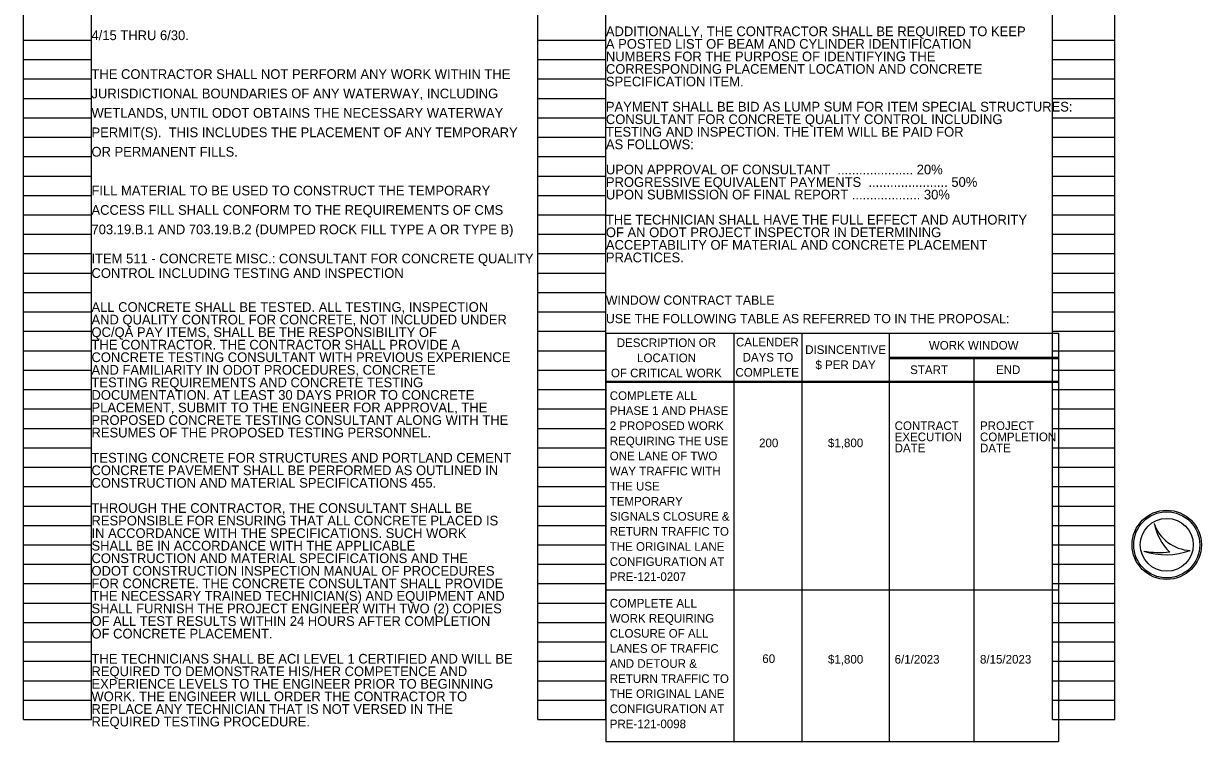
# Model space of a CAD drawing. Extents: x 0 to 78.9, y -24.2 to 22.
# Drawn here: x 61.9 to 78.89, y -23.54 to -13.19 of the extents above; entities that cross this region are included whole.
import ezdxf

# ---------------------------------------------------------------- set-up
doc = ezdxf.new("R2010")
doc.units = 0
doc.layers.add('SH_Data', color=7, linetype='Continuous')
doc.layers.add('SH_Text', color=7, linetype='Continuous')

msp = doc.modelspace()

# ---------------------------------------------------------------- linework, layer by layer
at = {"layer": 'SH_Data'}
for p, q in [((61.904, -23.228), (61.904, -3.068)), ((62.884, -23.228), (62.884, -3.068)), ((69.324, -23.228), (69.324, -3.068)), ((70.304, -23.228), (70.304, -3.068)), ((76.744, -23.228), (76.744, -3.068)), ((77.644, -23.228), (77.644, -3.068)), ((61.904, -13.428), (62.884, -13.428)), ((69.324, -13.428), (70.304, -13.428)), ((76.744, -13.428), (77.644, -13.428)), ((61.904, -13.708), (62.884, -13.708)), ((69.324, -13.708), (70.304, -13.708)), ((76.744, -13.708), (77.644, -13.708)), ((61.904, -13.988), (62.884, -13.988)), ((69.324, -13.988), (70.304, -13.988)), ((76.744, -13.988), (77.644, -13.988)), ((61.904, -14.268), (62.884, -14.268)), ((69.324, -14.268), (70.304, -14.268)), ((76.744, -14.268), (77.644, -14.268)), ((61.904, -14.548), (62.884, -14.548)), ((69.324, -14.548), (70.304, -14.548)), ((76.744, -14.548), (77.644, -14.548)), ((61.904, -14.828), (62.884, -14.828)), ((69.324, -14.828), (70.304, -14.828)), ((76.744, -14.828), (77.644, -14.828)), ((61.904, -15.108), (62.884, -15.108)), ((69.324, -15.108), (70.304, -15.108)), ((76.744, -15.108), (77.644, -15.108)), ((61.904, -15.388), (62.884, -15.388)), ((69.324, -15.388), (70.304, -15.388)), ((76.744, -15.388), (77.644, -15.388)), ((61.904, -15.668), (62.884, -15.668)), ((69.324, -15.668), (70.304, -15.668)), ((76.744, -15.668), (77.644, -15.668)), ((61.904, -15.948), (62.884, -15.948)), ((69.324, -15.948), (70.304, -15.948)), ((76.744, -15.948), (77.644, -15.948)), ((61.904, -16.228), (62.884, -16.228)), ((69.324, -16.228), (70.304, -16.228)), ((76.744, -16.228), (77.644, -16.228)), ((61.904, -16.508), (62.884, -16.508)), ((69.324, -16.508), (70.304, -16.508)), ((76.744, -16.508), (77.644, -16.508)), ((61.904, -16.788), (62.884, -16.788)), ((69.324, -16.788), (70.304, -16.788)), ((76.744, -16.788), (77.644, -16.788)), ((61.904, -17.068), (62.884, -17.068)), ((69.324, -17.068), (70.304, -17.068)), ((76.744, -17.068), (77.644, -17.068)), ((61.904, -17.348), (62.884, -17.348)), ((69.324, -17.348), (70.304, -17.348)), ((76.744, -17.348), (77.644, -17.348)), ((61.904, -17.628), (62.884, -17.628)), ((69.324, -17.628), (70.304, -17.628)), ((70.304, -17.657), (76.833, -17.657)), ((70.304, -17.657), (70.304, -23.544)), ((72.149, -17.657), (72.149, -18.46)), ((73.13, -17.657), (73.13, -18.46)), ((74.392, -17.657), (74.392, -18.46)), ((76.744, -17.628), (77.644, -17.628)), ((76.833, -17.657), (76.833, -18.477)), ((61.904, -17.908), (62.884, -17.908)), ((69.324, -17.908), (70.304, -17.908)), ((74.392, -18.002), (76.833, -18.002)), ((76.744, -17.908), (77.644, -17.908)), ((74.392, -18.02), (76.833, -18.02)), ((75.613, -18.02), (75.613, -23.544)), ((61.904, -18.188), (62.884, -18.188)), ((69.324, -18.188), (70.304, -18.188)), ((70.304, -18.347), (76.833, -18.347)), ((76.744, -18.188), (77.644, -18.188)), ((76.833, -18.347), (76.833, -23.544)), ((61.904, -18.468), (62.884, -18.468)), ((69.324, -18.468), (70.304, -18.468)), ((70.304, -18.364), (76.833, -18.364)), ((72.149, -18.364), (72.149, -23.544)), ((73.13, -18.364), (73.13, -23.544)), ((74.392, -18.364), (74.392, -23.544)), ((76.744, -18.468), (77.644, -18.468)), ((61.904, -18.748), (62.884, -18.748)), ((69.324, -18.748), (70.304, -18.748)), ((76.744, -18.748), (77.644, -18.748)), ((61.904, -19.028), (62.884, -19.028)), ((69.324, -19.028), (70.304, -19.028)), ((76.744, -19.028), (77.644, -19.028)), ((61.904, -19.308), (62.884, -19.308)), ((69.324, -19.308), (70.304, -19.308)), ((76.744, -19.308), (77.644, -19.308)), ((61.904, -19.588), (62.884, -19.588)), ((69.324, -19.588), (70.304, -19.588)), ((76.744, -19.588), (77.644, -19.588)), ((61.904, -19.868), (62.884, -19.868)), ((69.324, -19.868), (70.304, -19.868)), ((76.744, -19.868), (77.644, -19.868)), ((61.904, -20.148), (62.884, -20.148)), ((69.324, -20.148), (70.304, -20.148)), ((76.744, -20.148), (77.644, -20.148)), ((61.904, -20.428), (62.884, -20.428)), ((69.324, -20.428), (70.304, -20.428)), ((76.744, -20.428), (77.644, -20.428)), ((78.212, -20.398), (78.212, -20.398)), ((61.904, -20.708), (62.884, -20.708)), ((69.324, -20.708), (70.304, -20.708)), ((76.744, -20.708), (77.644, -20.708)), ((78.062, -20.798), (78.062, -20.798)), ((78.732, -20.789), (78.732, -20.789)), ((61.904, -20.988), (62.884, -20.988)), ((69.324, -20.988), (70.304, -20.988)), ((76.744, -20.988), (77.644, -20.988)), ((61.904, -21.268), (62.884, -21.268)), ((69.324, -21.268), (70.304, -21.268)), ((70.304, -21.358), (76.833, -21.358)), ((76.744, -21.268), (77.644, -21.268)), ((61.904, -21.548), (62.884, -21.548)), ((69.324, -21.548), (70.304, -21.548)), ((76.744, -21.548), (77.644, -21.548)), ((61.904, -21.828), (62.884, -21.828)), ((69.324, -21.828), (70.304, -21.828)), ((76.744, -21.828), (77.644, -21.828)), ((61.904, -22.108), (62.884, -22.108)), ((69.324, -22.108), (70.304, -22.108)), ((76.744, -22.108), (77.644, -22.108)), ((61.904, -22.388), (62.884, -22.388)), ((69.324, -22.388), (70.304, -22.388)), ((76.744, -22.388), (77.644, -22.388)), ((61.904, -22.668), (62.884, -22.668)), ((69.324, -22.668), (70.304, -22.668)), ((76.744, -22.668), (77.644, -22.668)), ((61.904, -22.948), (62.884, -22.948)), ((69.324, -22.948), (70.304, -22.948)), ((76.744, -22.948), (77.644, -22.948)), ((61.904, -23.228), (62.884, -23.228)), ((69.324, -23.228), (70.304, -23.228)), ((76.744, -23.228), (77.644, -23.228)), ((70.304, -23.544), (76.833, -23.544))]:
    msp.add_line(p, q, dxfattribs=at)
for radius in [0.5, 0.477, 0.477, 0.382]:
    msp.add_circle((78.394, -20.708), radius, dxfattribs=at)
for centre, radius, start, end in [((78.76, -20.21), 0.58, 198.9257, 198.9319), ((78.991, -20.238), 0.796, 191.6379, 191.6421), ((78.76, -20.21), 0.58, 198.9319, 267.1657), ((78.991, -20.238), 0.796, 191.6421, 226.0947), ((78.384, -19.838), 1.013, 251.4576, 290.0832), ((78.292, -19.553), 1.266, 259.4964, 259.4995), ((78.384, -19.838), 1.013, 251.4527, 251.4576), ((78.292, -19.553), 1.266, 259.4995, 276.6672)]:
    msp.add_arc(centre, radius, start, end, dxfattribs=at)

# ---------------------------------------------------------------- texts
at = {"layer": 'SH_Text'}
for s, height, p in [('ADDITIONALLY, THE CONTRACTOR SHALL BE REQUIRED TO KEEP', 0.14, (70.304, -13.371)), ('4/15 THRU 6/30.', 0.14, (62.884, -13.428)), ('A POSTED LIST OF BEAM AND CYLINDER IDENTIFICATION', 0.14, (70.304, -13.552)), ('NUMBERS FOR THE PURPOSE OF IDENTIFYING THE', 0.14, (70.304, -13.733)), ('THE CONTRACTOR SHALL NOT PERFORM ANY WORK WITHIN THE ', 0.14, (62.884, -13.988)), ('CORRESPONDING PLACEMENT LOCATION AND CONCRETE', 0.14, (70.304, -13.914)), ('SPECIFICATION ITEM.', 0.14, (70.304, -14.095)), ('JURISDICTIONAL BOUNDARIES OF ANY WATERWAY, INCLUDING ', 0.14, (62.884, -14.268)), ('WETLANDS, UNTIL ODOT OBTAINS THE NECESSARY WATERWAY ', 0.14, (62.884, -14.548)), ('PAYMENT SHALL BE BID AS LUMP SUM FOR ITEM SPECIAL STRUCTURES:', 0.14, (70.304, -14.458)), ('CONSULTANT FOR CONCRETE QUALITY CONTROL INCLUDING', 0.14, (70.304, -14.639)), ('PERMIT(S).\xa0 THIS INCLUDES THE PLACEMENT OF ANY TEMPORARY ', 0.14, (62.884, -14.828)), ('TESTING AND INSPECTION. THE ITEM WILL BE PAID FOR', 0.14, (70.304, -14.82)), ('AS FOLLOWS:', 0.14, (70.304, -15.001)), ('OR PERMANENT FILLS.', 0.14, (62.884, -15.108)), ('UPON APPROVAL OF CONSULTANT  ..................... 20%', 0.14, (70.304, -15.364)), ('PROGRESSIVE EQUIVALENT PAYMENTS  ...................... 50%', 0.14, (70.304, -15.545)), ('FILL MATERIAL TO BE USED TO CONSTRUCT THE TEMPORARY ', 0.14, (62.884, -15.668)), ('UPON SUBMISSION OF FINAL REPORT ................... 30%', 0.14, (70.304, -15.726)), ('ACCESS FILL SHALL CONFORM TO THE REQUIREMENTS OF CMS ', 0.14, (62.884, -15.948)), ('THE TECHNICIAN SHALL HAVE THE FULL EFFECT AND AUTHORITY', 0.14, (70.304, -16.088)), ('703.19.B.1 AND 703.19.B.2 (DUMPED ROCK FILL TYPE A OR TYPE B)', 0.14, (62.884, -16.228)), ('OF AN ODOT PROJECT INSPECTOR IN DETERMINING', 0.14, (70.304, -16.27)), ('ACCEPTABILITY OF MATERIAL AND CONCRETE PLACEMENT', 0.14, (70.304, -16.451)), ('ITEM 511 - CONCRETE MISC.: CONSULTANT FOR CONCRETE QUALITY', 0.14, (62.884, -16.648)), ('PRACTICES.', 0.14, (70.304, -16.632)), ('CONTROL INCLUDING TESTING AND INSPECTION', 0.14, (62.884, -16.858)), ('WINDOW CONTRACT TABLE', 0.133, (70.304, -17.245)), ('ALL CONCRETE SHALL BE TESTED. ALL TESTING, INSPECTION', 0.14, (62.884, -17.348)), ('AND QUALITY CONTROL FOR CONCRETE, NOT INCLUDED UNDER', 0.14, (62.884, -17.529)), ('USE THE FOLLOWING TABLE AS REFERRED TO IN THE PROPOSAL:', 0.133, (70.304, -17.511)), ('QC/QA PAY ITEMS, SHALL BE THE RESPONSIBILITY OF', 0.14, (62.884, -17.71)), ('THE CONTRACTOR. THE CONTRACTOR SHALL PROVIDE A', 0.14, (62.884, -17.891)), ('DESCRIPTION OR ', 0.12435, (70.461, -17.855)), ('CALENDER ', 0.1244, (72.18, -17.846)), ('DISINCENTIVE ', 0.12435, (73.179, -17.955)), ('WORK WINDOW', 0.12435, (74.963, -17.892)), ('CONCRETE TESTING CONSULTANT WITH PREVIOUS EXPERIENCE ', 0.14, (62.884, -18.072)), ('LOCATION', 0.1244, (70.754, -18.073)), ('DAYS TO ', 0.1244, (72.276, -18.064)), ('AND FAMILIARITY IN ODOT PROCEDURES, CONCRETE', 0.14, (62.884, -18.254)), ('OF CRITICAL WORK', 0.12435, (70.377, -18.291)), ('COMPLETE', 0.1244, (72.173, -18.282)), ('$ PER DAY', 0.1244, (73.327, -18.173)), ('START', 0.1244, (74.693, -18.245)), ('END', 0.1244, (75.931, -18.245)), ('TESTING REQUIREMENTS AND CONCRETE TESTING', 0.14, (62.884, -18.435)), ('DOCUMENTATION. AT LEAST 30 DAYS PRIOR TO CONCRETE', 0.14, (62.884, -18.616)), ('COMPLETE ALL ', 0.12435, (70.36, -18.618)), ('PLACEMENT, SUBMIT TO THE ENGINEER FOR APPROVAL, THE', 0.14, (62.884, -18.797)), ('PROPOSED CONCRETE TESTING CONSULTANT ALONG WITH THE', 0.14, (62.884, -18.978)), ('PHASE 1 AND PHASE ', 0.12435, (70.36, -18.835)), ('RESUMES OF THE PROPOSED TESTING PERSONNEL.', 0.14, (62.884, -19.159)), ('2 PROPOSED WORK ', 0.12435, (70.36, -19.053)), ('CONTRACT', 0.1244, (74.469, -19.052)), ('PROJECT ', 0.1244, (75.7, -19.052)), ('REQUIRING THE USE  ', 0.12435, (70.36, -19.271)), ('200', 0.1244, (72.514, -19.3)), ('$1,800', 0.1244, (73.507, -19.3)), ('EXECUTION', 0.1244, (74.469, -19.213)), ('COMPLETION ', 0.12435, (75.7, -19.213)), ('ONE LANE OF TWO ', 0.12435, (70.36, -19.488)), ('DATE', 0.1244, (74.469, -19.374)), ('DATE', 0.1244, (75.7, -19.374)), ('TESTING CONCRETE FOR STRUCTURES AND PORTLAND CEMENT', 0.14, (62.884, -19.522)), ('CONCRETE PAVEMENT SHALL BE PERFORMED AS OUTLINED IN', 0.14, (62.884, -19.703)), ('WAY TRAFFIC WITH ', 0.12435, (70.36, -19.706)), ('CONSTRUCTION AND MATERIAL SPECIFICATIONS 455.', 0.14, (62.884, -19.884)), ('THE USE  ', 0.1244, (70.36, -19.924)), ('TEMPORARY ', 0.1244, (70.36, -20.141)), ('THROUGH THE CONTRACTOR, THE CONSULTANT SHALL BE', 0.14, (62.884, -20.247)), ('RESPONSIBLE FOR ENSURING THAT ALL CONCRETE PLACED IS', 0.14, (62.884, -20.428)), ('SIGNALS CLOSURE & ', 0.12435, (70.36, -20.359)), ('IN ACCORDANCE WITH THE SPECIFICATIONS. SUCH WORK', 0.14, (62.884, -20.609)), ('RETURN TRAFFIC TO ', 0.12435, (70.36, -20.576)), ('SHALL BE IN ACCORDANCE WITH THE APPLICABLE', 0.14, (62.884, -20.79)), ('THE ORIGINAL LANE ', 0.12435, (70.36, -20.794)), ('CONSTRUCTION AND MATERIAL SPECIFICATIONS AND THE', 0.14, (62.884, -20.971)), ('CONFIGURATION AT ', 0.12435, (70.36, -21.012)), ('ODOT CONSTRUCTION INSPECTION MANUAL OF PROCEDURES', 0.14, (62.884, -21.153)), ('FOR CONCRETE. THE CONCRETE CONSULTANT SHALL PROVIDE', 0.14, (62.884, -21.334)), ('PRE-121-0207', 0.12435, (70.36, -21.229)), ('THE NECESSARY TRAINED TECHNICIAN(S) AND EQUIPMENT AND', 0.14, (62.884, -21.515)), ('SHALL FURNISH THE PROJECT ENGINEER WITH TWO (2) COPIES', 0.14, (62.884, -21.696)), ('COMPLETE ALL ', 0.12435, (70.36, -21.612)), ('OF ALL TEST RESULTS WITHIN 24 HOURS AFTER COMPLETION', 0.14, (62.884, -21.877)), ('WORK REQUIRING ', 0.12435, (70.36, -21.83)), ('OF CONCRETE PLACEMENT.', 0.14, (62.884, -22.059)), ('CLOSURE OF ALL ', 0.12435, (70.36, -22.047)), ('LANES OF TRAFFIC ', 0.12435, (70.36, -22.265)), ('THE TECHNICIANS SHALL BE ACI LEVEL 1 CERTIFIED AND WILL BE', 0.14, (62.884, -22.421)), ('AND DETOUR & ', 0.12435, (70.36, -22.482)), ('60', 0.1244, (72.56, -22.412)), ('$1,800', 0.1244, (73.507, -22.421)), ('6/1/2023', 0.1244, (74.469, -22.421)), ('8/15/2023', 0.1244, (75.7, -22.421)), ('REQUIRED TO DEMONSTRATE HIS/HER COMPETENCE AND', 0.14, (62.884, -22.602)), ('RETURN TRAFFIC TO ', 0.12435, (70.36, -22.7)), ('EXPERIENCE LEVELS TO THE ENGINEER PRIOR TO BEGINNING', 0.14, (62.884, -22.783)), ('WORK. THE ENGINEER WILL ORDER THE CONTRACTOR TO ', 0.14, (62.884, -22.964)), ('THE ORIGINAL LANE ', 0.12435, (70.36, -22.918)), ('REPLACE ANY TECHNICIAN THAT IS NOT VERSED IN THE ', 0.14, (62.884, -23.146)), ('CONFIGURATION AT ', 0.12435, (70.36, -23.135)), ('REQUIRED TESTING PROCEDURE.', 0.14, (62.884, -23.327)), ('PRE-121-0098', 0.12435, (70.36, -23.353))]:
    msp.add_text(s, height=height, dxfattribs=at).set_placement(p)

doc.saveas('drawing.dxf')
